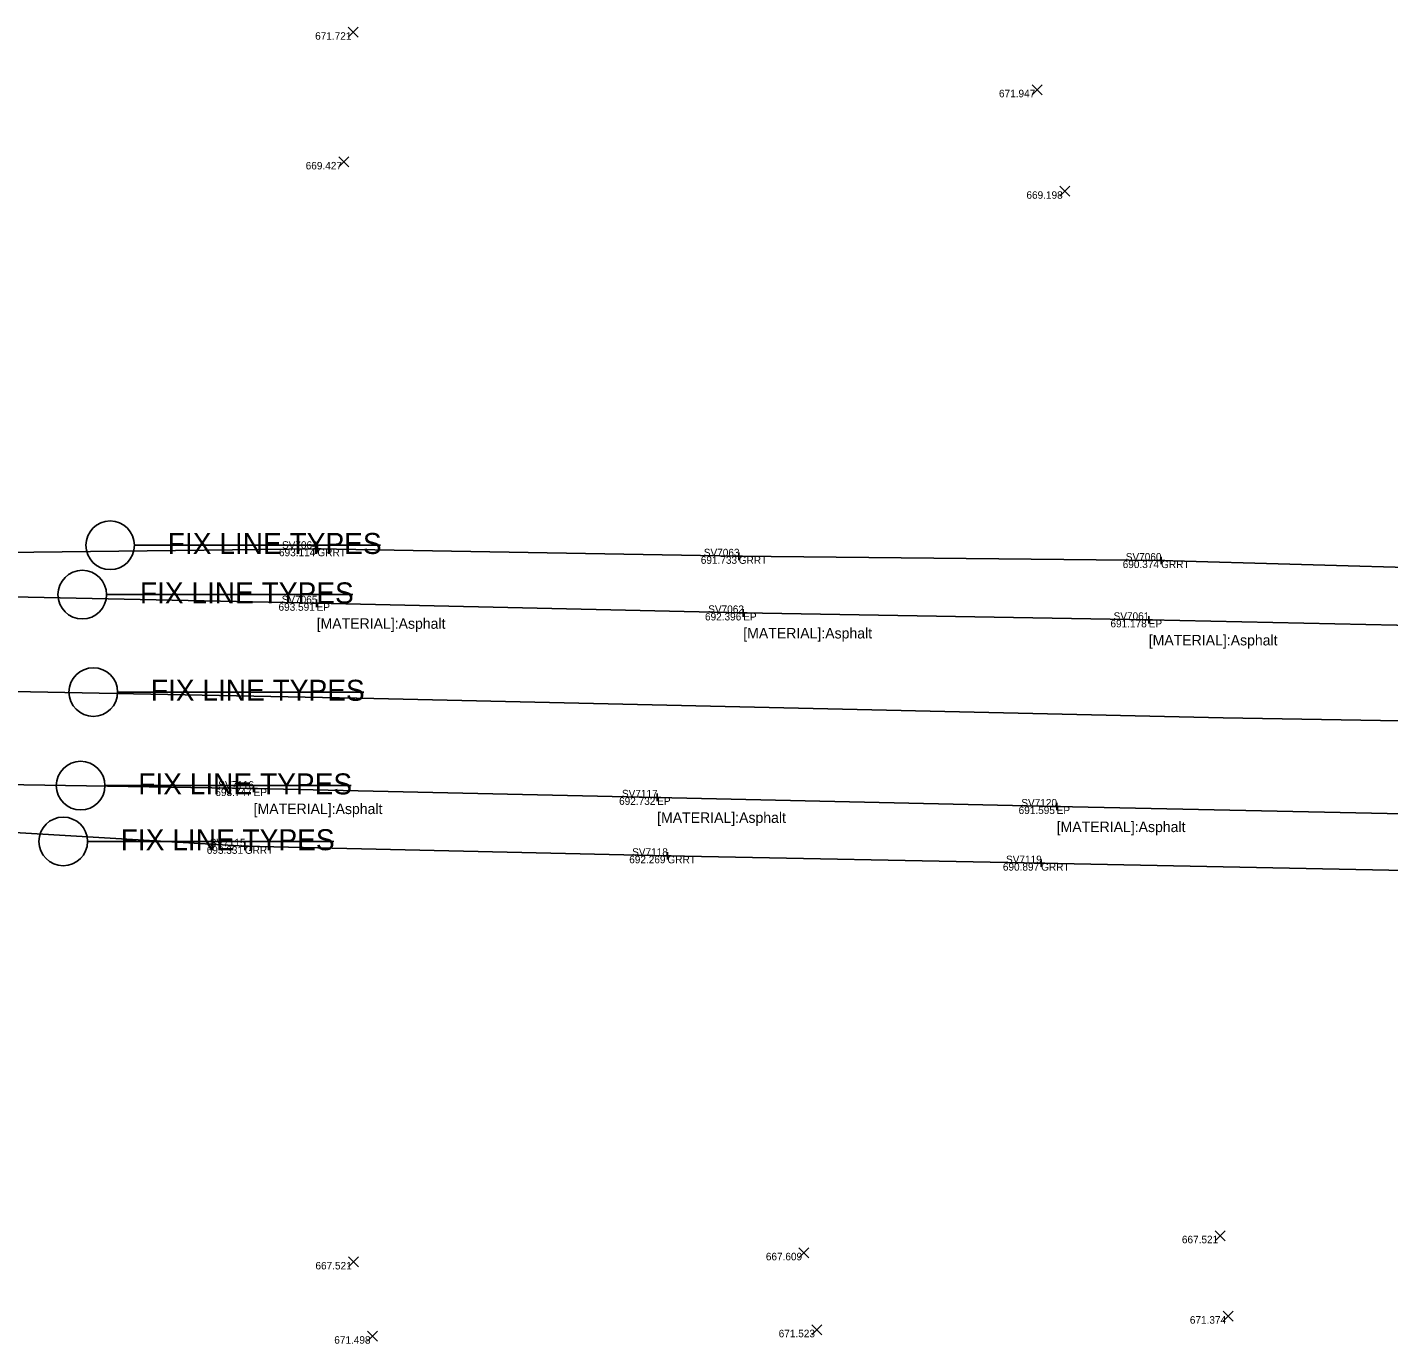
# Model space of a CAD drawing. Extents: x 1659932 to 1663108, y 619867 to 620611.
# Drawn here: x 1661623.8 to 1661805.2, y 620139.4 to 620314.9 of the extents above; entities that cross this region are included whole.
import ezdxf

# ---------------------------------------------------------------- set-up
doc = ezdxf.new("R2010")
doc.units = 0
for name, color, linetype in [('PM_X_CL_Dashed', 7, 'Continuous'), ('PV_X_EOP', 7, 'Continuous'), ('RD_X_GR_Rt', 7, 'Continuous'), ('SC_Scratch6', 7, 'Continuous'), ('SV_X_Random_Point', 7, 'Continuous'), ('SV_X_Shot_Marker', 7, 'Continuous'), ('SV_X_Text', 7, 'Continuous'), ('SV_X_Text_Comment', 7, 'Continuous'), ('SV_X_Text_Elevation', 7, 'Continuous'), ('SV_X_Text_Name', 7, 'Continuous')]:
    doc.layers.add(name, color=color, linetype=linetype)

msp = doc.modelspace()

# ---------------------------------------------------------------- linework, layer by layer
at = {"layer": 'PM_X_CL_Dashed'}
msp.add_lwpolyline([(1661548.68, 620227.77), (1661669.96, 620225.42), (1661783.14, 620222.83), (1661893.22, 620220.99), (1661995.64, 620218.69), (1662098.65, 620216.83), (1662208.49, 620214.49), (1662310.47, 620212.73), (1662401.36, 620210.77), (1662501.77, 620209.17), (1662614.52, 620207.13), (1662727.83, 620205.67), (1662841.02, 620204.32), (1662955.43, 620202.56), (1663049.21, 620201.36)], dxfattribs=at)
at = {"layer": 'PV_X_EOP'}
for points in [[(1662111.67, 620229.32), (1662054.93, 620230.37), (1661998.42, 620231.32), (1661945.73, 620232.16), (1661885.47, 620233.5), (1661831.11, 620234.65), (1661773.24, 620235.9), (1661719.2, 620236.82), (1661662.34, 620238.11), (1661602.46, 620239.35), (1661551.29, 620241.52)], [(1661543.6, 620215.08), (1661595.45, 620214.35), (1661653.94, 620213.41), (1661707.72, 620212.24), (1661760.97, 620211.02), (1661840.69, 620209.32), (1661897.28, 620208.31), (1661955.8, 620207.5), (1662009.84, 620206.22), (1662063.33, 620205.17), (1662115.71, 620204.21)]]:
    msp.add_lwpolyline(points, dxfattribs=at)
at = {"layer": 'RD_X_GR_Rt'}
for points in [[(1662112.15, 620237.06), (1662055.66, 620238.25), (1661999.68, 620239.27), (1661943.73, 620240.2), (1661887.33, 620241.47), (1661831.01, 620242.22), (1661774.89, 620243.8), (1661718.6, 620244.37), (1661662.44, 620245.38), (1661601.89, 620244.64), (1661537.84, 620244.62)], [(1661527.71, 620211.76), (1661596.63, 620209.07), (1661652.77, 620205.71), (1661709.09, 620204.45), (1661758.9, 620203.47), (1661840.54, 620201.81), (1661896.27, 620200.97), (1661955.33, 620199.48), (1662008.56, 620198.59), (1662063.03, 620197.38), (1662114.92, 620196.42)]]:
    msp.add_lwpolyline(points, dxfattribs=at)
at = {"layer": 'SC_Scratch6'}
for p, q in [((1661638.07, 620245.84), (1661670.87, 620245.84)), ((1661634.35, 620239.26), (1661667.15, 620239.26)), ((1661635.81, 620226.27), (1661668.62, 620226.27)), ((1661634.13, 620213.8), (1661666.93, 620213.8)), ((1661631.8, 620206.36), (1661664.61, 620206.36))]:
    msp.add_line(p, q, dxfattribs=at)
for centre in [(1661634.82, 620245.84), (1661631.1, 620239.26), (1661632.57, 620226.27), (1661630.88, 620213.8), (1661628.56, 620206.36)]:
    msp.add_circle(centre, 3.24, dxfattribs=at)
at = {"layer": 'SV_X_Random_Point'}
for p, q in [((1661666.55, 620313.56), (1661667.89, 620314.9)), ((1661666.55, 620314.9), (1661667.89, 620313.56)), ((1661757.71, 620305.89), (1661759.04, 620307.23)), ((1661757.71, 620307.23), (1661759.04, 620305.89)), ((1661665.31, 620296.28), (1661666.64, 620297.61)), ((1661665.31, 620297.61), (1661666.64, 620296.28)), ((1661761.38, 620292.36), (1661762.71, 620293.7)), ((1661761.38, 620293.7), (1661762.71, 620292.36)), ((1661782.08, 620153.14), (1661783.41, 620154.47)), ((1661782.08, 620154.47), (1661783.41, 620153.14)), ((1661666.6, 620149.64), (1661667.93, 620150.98)), ((1661666.6, 620150.98), (1661667.93, 620149.64)), ((1661726.62, 620150.86), (1661727.96, 620152.19)), ((1661726.62, 620152.19), (1661727.96, 620150.86)), ((1661783.17, 620142.41), (1661784.51, 620143.74)), ((1661783.17, 620143.74), (1661784.51, 620142.41)), ((1661728.32, 620140.6), (1661729.65, 620141.93)), ((1661728.32, 620141.93), (1661729.65, 620140.6)), ((1661669.13, 620139.75), (1661670.46, 620141.08)), ((1661669.13, 620141.08), (1661670.46, 620139.75))]:
    msp.add_line(p, q, dxfattribs=at)
at = {"layer": 'SV_X_Shot_Marker'}
for p, q in [((1661661.94, 620245.38), (1661662.94, 620245.38)), ((1661662.44, 620245.88), (1661662.44, 620244.88)), ((1661662.44, 620245.38), (1661662.44, 620245.38)), ((1661718.1, 620244.37), (1661719.1, 620244.37)), ((1661718.6, 620244.87), (1661718.6, 620243.87)), ((1661718.6, 620244.37), (1661718.6, 620244.37)), ((1661774.39, 620243.8), (1661775.39, 620243.8)), ((1661774.89, 620244.3), (1661774.89, 620243.3)), ((1661774.89, 620243.8), (1661774.89, 620243.8)), ((1661661.84, 620238.11), (1661662.84, 620238.11)), ((1661662.34, 620238.61), (1661662.34, 620237.61)), ((1661662.34, 620238.11), (1661662.34, 620238.11)), ((1661718.7, 620236.82), (1661719.7, 620236.82)), ((1661719.2, 620237.32), (1661719.2, 620236.32)), ((1661719.2, 620236.82), (1661719.2, 620236.82)), ((1661773.24, 620236.4), (1661773.24, 620235.4)), ((1661772.74, 620235.9), (1661773.74, 620235.9)), ((1661773.24, 620235.9), (1661773.24, 620235.9)), ((1661653.44, 620213.41), (1661654.44, 620213.41)), ((1661653.94, 620213.91), (1661653.94, 620212.91)), ((1661653.94, 620213.41), (1661653.94, 620213.41)), ((1661707.72, 620212.74), (1661707.72, 620211.74)), ((1661707.22, 620212.24), (1661708.22, 620212.24)), ((1661707.72, 620212.24), (1661707.72, 620212.24)), ((1661760.47, 620211.02), (1661761.47, 620211.02)), ((1661760.97, 620211.52), (1661760.97, 620210.52)), ((1661760.97, 620211.02), (1661760.97, 620211.02)), ((1661652.27, 620205.71), (1661653.27, 620205.71)), ((1661652.77, 620206.21), (1661652.77, 620205.21)), ((1661652.77, 620205.71), (1661652.77, 620205.71)), ((1661708.59, 620204.45), (1661709.59, 620204.45)), ((1661709.09, 620204.95), (1661709.09, 620203.95)), ((1661709.09, 620204.45), (1661709.09, 620204.45)), ((1661758.4, 620203.47), (1661759.4, 620203.47)), ((1661758.9, 620203.97), (1661758.9, 620202.97)), ((1661758.9, 620203.47), (1661758.9, 620203.47))]:
    msp.add_line(p, q, dxfattribs=at)

# ---------------------------------------------------------------- texts
at = {"layer": 'SC_Scratch6'}
for p in [(1661642.5, 620244.68), (1661638.78, 620238.09), (1661640.24, 620225.11), (1661638.56, 620212.63), (1661636.23, 620205.19)]:
    msp.add_text('FIX LINE TYPES', height=2.8, dxfattribs=at).set_placement(p)
at = {"layer": 'SV_X_Text'}
for p in [(1661662.34, 620234.71), (1661719.2, 620233.42), (1661773.24, 620232.49), (1661653.94, 620210.01), (1661707.72, 620208.84), (1661760.97, 620207.61)]:
    msp.add_text('[MATERIAL]:Asphalt', height=1.4, dxfattribs=at).set_placement(p)
at = {"layer": 'SV_X_Text_Comment'}
for s, p in [('GRRT', (1661662.44, 620244.38)), ('GRRT', (1661718.6, 620243.37)), ('GRRT', (1661774.89, 620242.8)), ('EP', (1661662.34, 620237.11)), ('EP', (1661719.2, 620235.82)), ('EP', (1661773.24, 620234.9)), ('EP', (1661653.94, 620212.41)), ('EP', (1661707.72, 620211.24)), ('EP', (1661760.97, 620210.02)), ('GRRT', (1661652.77, 620204.71)), ('GRRT', (1661709.09, 620203.45)), ('GRRT', (1661758.9, 620202.47))]:
    msp.add_text(s, height=1, dxfattribs=at).set_placement(p)
at = {"layer": 'SV_X_Text_Elevation'}
for s, p in [('671.721', (1661662.14, 620313.23)), ('671.947', (1661753.28, 620305.56)), ('669.427', (1661660.88, 620295.94)), ('669.198', (1661756.94, 620292.03)), ('693.114', (1661657.32, 620244.38)), ('691.733', (1661713.54, 620243.37)), ('690.374', (1661769.77, 620242.8)), ('693.591', (1661657.26, 620237.11)), ('692.396', (1661714.1, 620235.82)), ('691.178', (1661768.14, 620234.9)), ('693.747', (1661648.84, 620212.41)), ('692.732', (1661702.65, 620211.24)), ('691.595', (1661755.9, 620210.02)), ('693.331', (1661647.69, 620204.71)), ('692.269', (1661704, 620203.45)), ('690.897', (1661753.8, 620202.47)), ('667.521', (1661777.66, 620152.8)), ('667.609', (1661722.21, 620150.53)), ('667.521', (1661662.18, 620149.31)), ('671.374', (1661778.72, 620142.08)), ('671.498', (1661664.69, 620139.41)), ('671.523', (1661723.92, 620140.27))]:
    msp.add_text(s, height=1, dxfattribs=at).set_placement(p)
at = {"layer": 'SV_X_Text_Name'}
for s, p in [('SV7064', (1661657.72, 620245.38)), ('SV7063', (1661713.94, 620244.37)), ('SV7060', (1661770.18, 620243.8)), ('SV7065', (1661657.68, 620238.11)), ('SV7062', (1661714.53, 620236.82)), ('SV7061', (1661768.56, 620235.9)), ('SV7116', (1661649.23, 620213.41)), ('SV7117', (1661703.03, 620212.24)), ('SV7120', (1661756.26, 620211.02)), ('SV7115', (1661648.1, 620205.71)), ('SV7118', (1661704.39, 620204.45)), ('SV7119', (1661754.22, 620203.47))]:
    msp.add_text(s, height=1, dxfattribs=at).set_placement(p)

doc.saveas('drawing.dxf')
